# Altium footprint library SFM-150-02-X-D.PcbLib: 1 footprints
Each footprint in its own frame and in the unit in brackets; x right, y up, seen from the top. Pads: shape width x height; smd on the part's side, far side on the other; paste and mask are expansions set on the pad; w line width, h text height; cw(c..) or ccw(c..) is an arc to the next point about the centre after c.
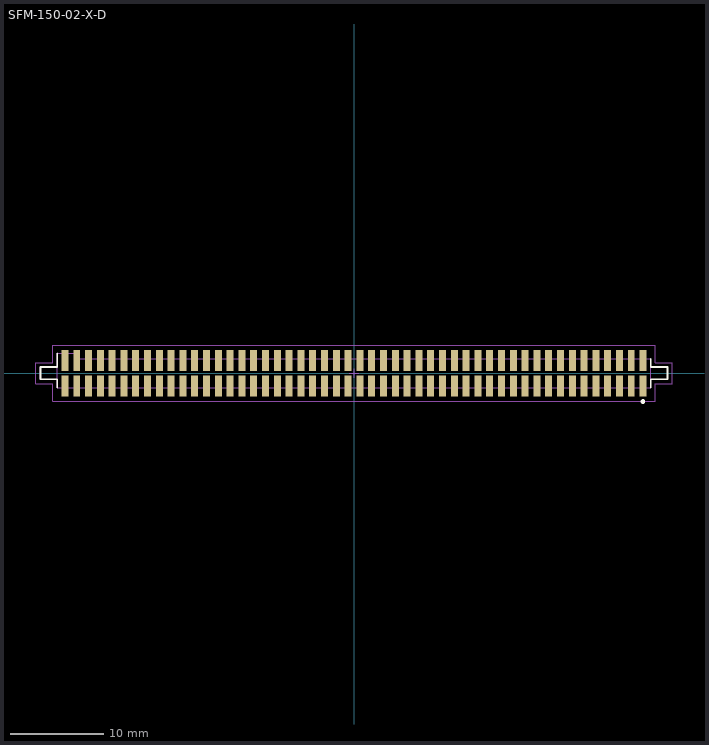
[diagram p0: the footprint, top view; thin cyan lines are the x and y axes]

## SFM-150-02-X-D [mm] "1.27mm pitch, 100 pin, socket strip; SMT"
height 4.57
pads (100):
  rect 0.75x2.25 smd mask+0: 1(31.115,-1.375) 2(31.115,1.375) 3(29.845,-1.375) 4(29.845,1.375) 5(28.575,-1.375) 6(28.575,1.375) 7(27.305,-1.375) 8(27.305,1.375) 9(26.035,-1.375) 10(26.035,1.375) 11(24.765,-1.375) 12(24.765,1.375) 13(23.495,-1.375) 14(23.495,1.375) 15(22.225,-1.375) 16(22.225,1.375) 17(20.955,-1.375) 18(20.955,1.375) 19(19.685,-1.375) 20(19.685,1.375) 21(18.415,-1.375) 22(18.415,1.375) 23(17.145,-1.375) 24(17.145,1.375) 25(15.875,-1.375) 26(15.875,1.375) 27(14.605,-1.375) 28(14.605,1.375) 29(13.335,-1.375) 30(13.335,1.375) 31(12.065,-1.375) 32(12.065,1.375) 33(10.795,-1.375) 34(10.795,1.375) 35(9.525,-1.375) 36(9.525,1.375) 37(8.255,-1.375) 38(8.255,1.375) 39(6.985,-1.375) 40(6.985,1.375) 41(5.715,-1.375) 42(5.715,1.375) 43(4.445,-1.375) 44(4.445,1.375) 45(3.175,-1.375) 46(3.175,1.375) 47(1.905,-1.375) 48(1.905,1.375) 49(0.635,-1.375) 50(0.635,1.375) 51(-0.635,-1.375) 52(-0.635,1.375) 53(-1.905,-1.375) 54(-1.905,1.375) 55(-3.175,-1.375) 56(-3.175,1.375) 57(-4.445,-1.375) 58(-4.445,1.375) 59(-5.715,-1.375) 60(-5.715,1.375) 61(-6.985,-1.375) 62(-6.985,1.375) 63(-8.255,-1.375) 64(-8.255,1.375) 65(-9.525,-1.375) 66(-9.525,1.375) 67(-10.795,-1.375) 68(-10.795,1.375) 69(-12.065,-1.375) 70(-12.065,1.375) 71(-13.335,-1.375) 72(-13.335,1.375) 73(-14.605,-1.375) 74(-14.605,1.375) 75(-15.875,-1.375) 76(-15.875,1.375) 77(-17.145,-1.375) 78(-17.145,1.375) 79(-18.415,-1.375) 80(-18.415,1.375) 81(-19.685,-1.375) 82(-19.685,1.375) 83(-20.955,-1.375) 84(-20.955,1.375) 85(-22.225,-1.375) 86(-22.225,1.375) 87(-23.495,-1.375) 88(-23.495,1.375) 89(-24.765,-1.375) 90(-24.765,1.375) 91(-26.035,-1.375) 92(-26.035,1.375) 93(-27.305,-1.375) 94(-27.305,1.375) 95(-28.575,-1.375) 96(-28.575,1.375) 97(-29.845,-1.375) 98(-29.845,1.375) 99(-31.115,-1.375) 100(-31.115,1.375)
Top Overlay:
  circle w0.25: c31.1,-3.05 r0.125
  lines w0.2: -31.95,-1.55 -31.95,-0.65 -33.75,-0.65 -33.75,0.65 -31.95,0.65 -31.95,2.15 ; 31.95,-1.55 31.95,-0.65 33.75,-0.65 33.75,0.65 31.95,0.65 31.95,1.55
Mechanical 12:
  lines w0.001: -33.75,-0.65 -31.95,-0.65 -31.95,-1.55 31.95,-1.55 31.95,-0.65 33.75,-0.65 33.75,0.65 31.95,0.65 31.95,1.55 -29.9,1.55 -29.9,2.15 -31.95,2.15 -31.95,0.65 -33.75,0.65 -33.75,-0.65
Mechanical 13:
  lines w0.1: -31.95,-0.65 -31.95,-1.55 31.95,-1.55 31.95,-0.65 ; -31.95,-0.65 -33.75,-0.65 -33.75,0.65 -31.95,0.65 ; -31.95,-0.65 -31.95,0.65 ; -31.95,0.65 -31.95,2.15 -29.9,2.15 -29.9,1.55 31.95,1.55 31.95,0.65 ; 31.95,-0.65 33.75,-0.65 33.75,0.65 31.95,0.65 ; 31.95,-0.65 31.95,0.65
  text ".Designator" at 0,-0.127 h1.52
Mechanical 15:
  lines w0.05: -0.5,0 0.5,0 ; 0,-0.5 0,0.5 ; -34.25,-1.15 -34.25,1.15 -32.45,1.15 -32.45,3 32.45,3 32.45,1.15 34.25,1.15 34.25,-1.15 32.45,-1.15 32.45,-3 -32.45,-3 -32.45,-1.15 -34.25,-1.15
